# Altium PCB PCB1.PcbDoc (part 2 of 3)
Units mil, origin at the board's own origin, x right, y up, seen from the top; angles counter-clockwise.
Board outline 3586 x 4364 mil, 2 copper layers (Top Layer, Bottom Layer); 0 components, 57 nets, 205 pads, 0 vias.
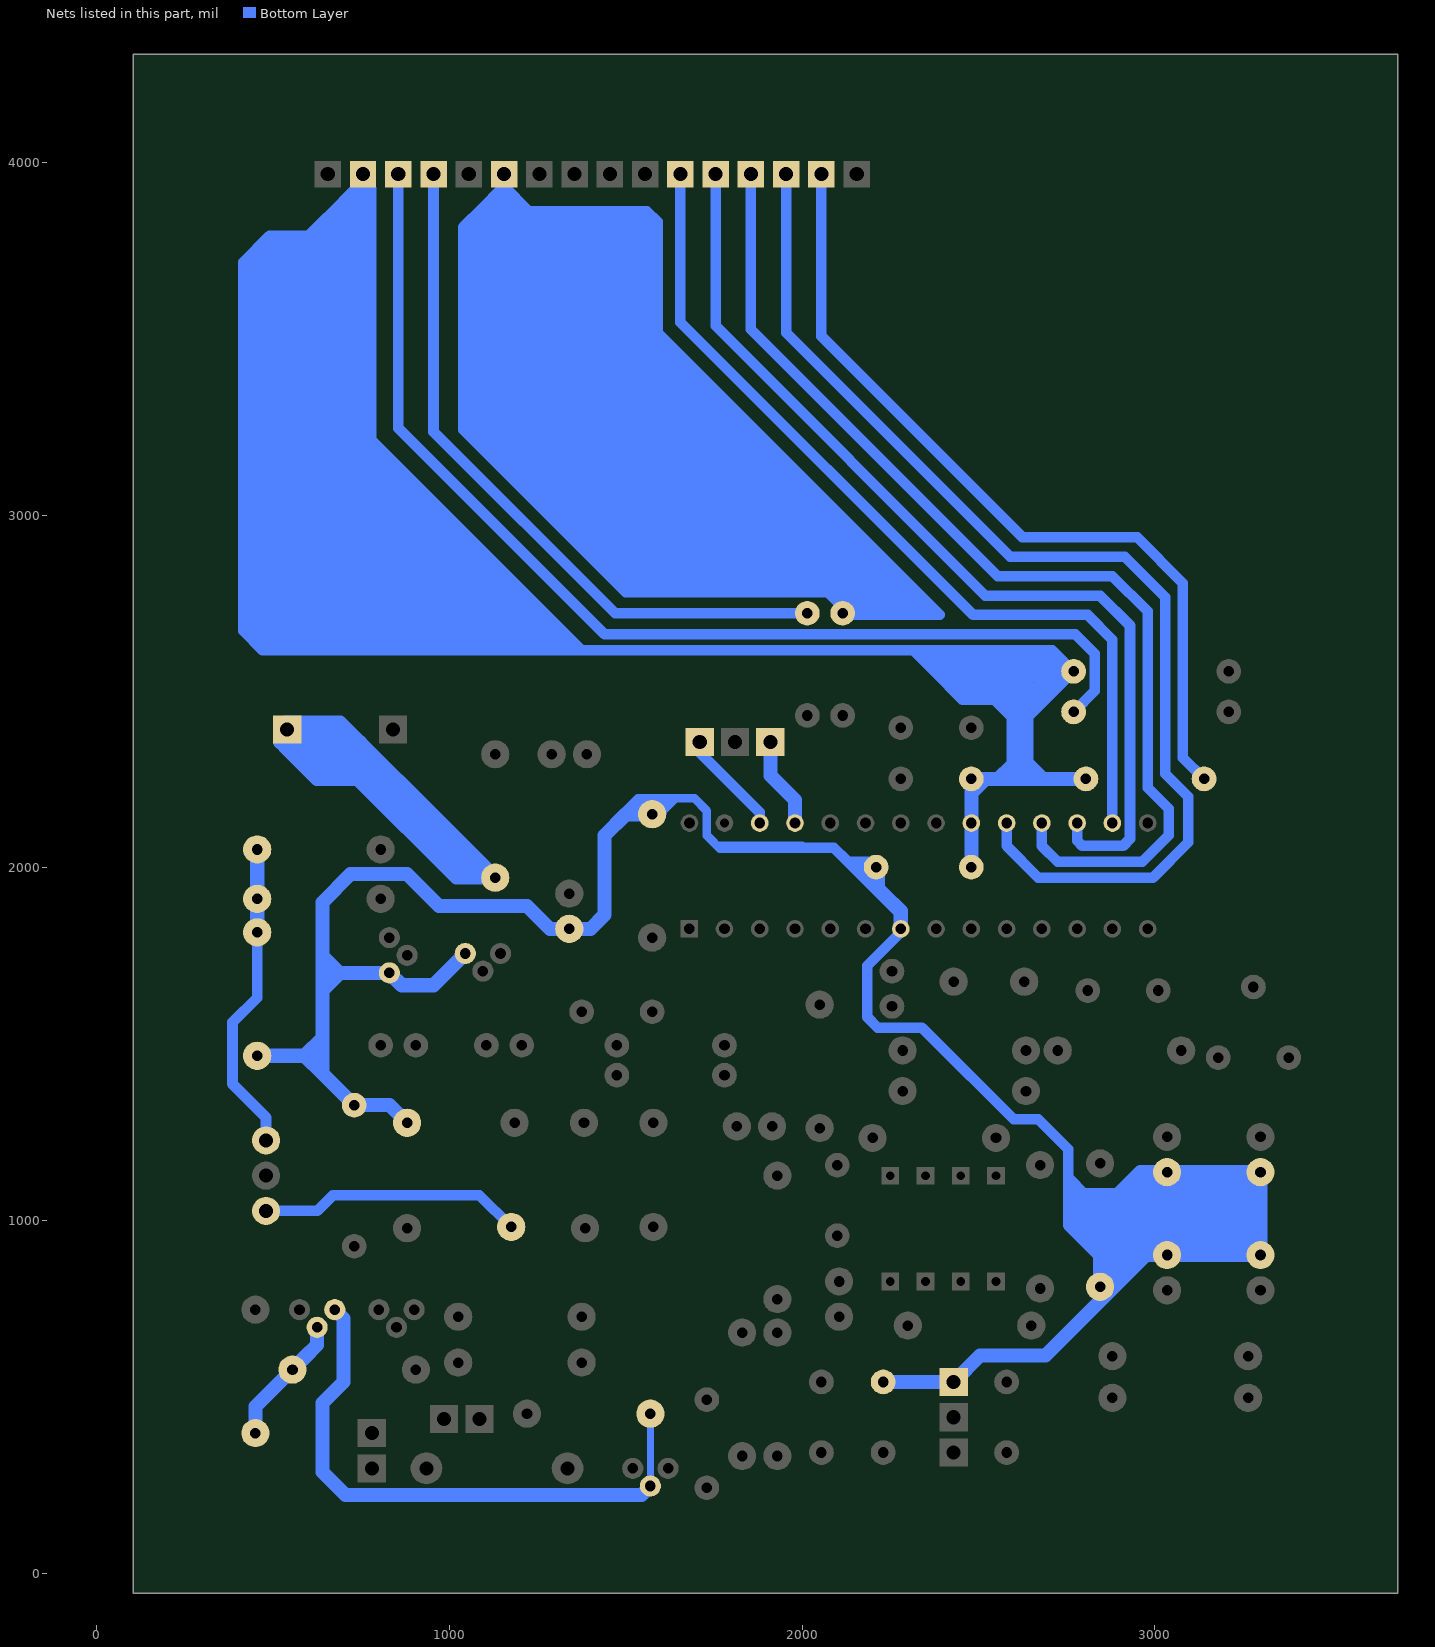
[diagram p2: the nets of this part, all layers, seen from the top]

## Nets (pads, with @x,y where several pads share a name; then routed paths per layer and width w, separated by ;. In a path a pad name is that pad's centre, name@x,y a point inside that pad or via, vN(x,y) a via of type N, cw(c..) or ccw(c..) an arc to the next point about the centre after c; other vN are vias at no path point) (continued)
$Net5: pad.1@454.35,1466.74 pad.1@729.35,1326.74 pad.1@829.35,1701.74 pad.1@879.35,1276.74 pad.1@1044.35,1756.74 pad.1@1339.35,1826.74 pad.1@1574.35,2151.74 pad.1@2209.35,2001.74 pad.1@2229.35,541.74 pad.1@2279.35,1826.74 pad.1@2429.35,541.74 pad.1@2844.35,811.74 pad.1@3034.35,901.74 pad.1@3034.35,1136.74 pad.1@3299.35,901.74 pad.1@3299.35,1136.74 | length 14800.9
  Bottom Layer w20: 2129.35,2021.74 2149.35,2021.74 ; 2134.35,2011.74 2159.35,2011.74 ; pad.1@2199.35,1971.74 2169.35,2001.74 2159.35,2011.74 ; pad.1@2214.35,2021.74 2149.35,2021.74 ; 2224.35,1941.74 2224.35,1946.74 2224.35,1966.74 ; pad.1@2224.35,2006.74 2224.35,2001.74 2224.35,1966.74 ; 2149.35,2021.74 2159.35,2011.74 ; 2159.35,2011.74 2174.35,2011.74 pad.1@2209.35,2001.74 2224.35,1966.74
  Bottom Layer w25: 1489.35,2151.74 1534.35,2196.74 1544.35,2196.74 1604.35,2196.74 1619.35,2196.74 ; 1524.35,2151.74 pad.1@1543.65,2171.04 ; 1529.35,2176.74 1534.35,2176.74 pad.1@1543.65,2171.04 ; 1564.35,2191.74 pad.1@1543.65,2171.04 ; pad.1@1589.35,2146.74 1614.35,2171.74 ; 1804.35,2054.74 1766.35,2054.74 1759.35,2061.74 ; 1999.35,2056.74 1999.35,2061.74 1759.35,2061.74 ; pad.1@1543.65,2171.04 pad.1@1574.35,2151.74 ; pad.1@1574.35,2151.74 1614.35,2171.74 ; pad.1@1574.35,2151.74 1614.35,2176.74 1634.35,2196.74 ; pad.1@1574.35,2151.74 1609.35,2186.74 1619.35,2196.74 ; 1614.35,2171.74 1624.35,2181.74 1639.35,2196.74 ; 1619.35,2196.74 1629.35,2196.74 1634.35,2196.74 ; 1634.35,2196.74 1639.35,2196.74 ; 1639.35,2196.74 1659.35,2196.74 1664.35,2196.74 1694.35,2196.74 1729.35,2161.74 1729.35,2091.74 1743.35,2077.74 1759.35,2061.74
  Bottom Layer w30: 1769.35,2056.74 1999.35,2056.74 2089.35,2056.74 2124.35,2021.74 2134.35,2011.74 2144.35,2001.74 ; pad.1@2224.35,2001.74 pad.1@2209.35,2001.74 2169.35,2001.74 2144.35,2001.74 ; pad.1@2274.35,1821.74 pad.1@2279.35,1826.74 2279.35,1816.74 2184.35,1721.74 2184.35,1576.74 2214.35,1546.74 2339.35,1546.74 2359.35,1526.74 2599.35,1286.74 2669.35,1286.74 2754.35,1201.74 2754.35,1121.74 ; 2279.35,1866.74 2144.35,2001.74 ; 2754.35,1006.74 2754.35,1061.74 ; 2764.35,1091.74 2794.35,1061.74 ; 2809.35,1046.74 2794.35,1061.74 ; 2824.35,1051.74 2814.35,1061.74 ; 2844.35,856.74 2844.35,861.74 ; 2889.35,1061.74 2814.35,1061.74 ; 2754.35,1061.74 2754.35,1086.74 2754.35,1121.74 ; 2754.35,1061.74 2759.35,1061.74 2794.35,1061.74 ; 2754.35,1121.74 2804.35,1071.74 2814.35,1061.74 ; 2794.35,1061.74 2804.35,1061.74 2814.35,1061.74
  Bottom Layer w40: pad.1@454.35,1466.74 589.35,1466.74 ; pad.1@879.35,1276.74 829.35,1326.74 764.35,1326.74 pad.1@729.35,1326.74 649.35,1406.74 639.35,1416.74 ; pad.1@1044.35,1756.74 954.35,1666.74 924.35,1666.74 899.35,1666.74 864.35,1666.74 pad.1@829.35,1701.74 689.35,1701.74 ; pad.1@1574.35,2151.74 1524.35,2151.74 1499.35,2151.74 1439.35,2091.74 1439.35,1866.74 1399.35,1826.74 pad.1@1339.35,1826.74 1284.35,1826.74 1219.35,1891.74 969.35,1891.74 879.35,1981.74 719.35,1981.74 639.35,1901.74 639.35,1749.24 ; 2159.35,1996.74 2209.35,1946.74 ; pad.1@2209.35,2001.74 2209.35,1946.74 ; pad.1@2229.35,541.74 pad.1@2429.35,541.74 2504.35,616.74 2689.35,616.74 2844.35,771.74 ; pad.1@2279.35,1826.74 2279.35,1846.74 2279.35,1866.74 2279.35,1876.74 2231.85,1924.24 2209.35,1946.74 ; 2759.35,1061.74 2759.35,1031.74 2759.35,986.74 2844.35,901.74 ; 2769.35,1011.74 2844.35,936.74 ; 2774.35,1056.74 2844.35,986.74 ; 2844.35,856.74 pad.1@2844.35,811.74 ; 2854.35,966.74 2864.35,966.74 ; 2854.35,1001.74 2864.35,1001.74 ; 2859.35,931.74 2974.35,931.74 ; 2859.35,1026.74 2924.35,1026.74 ; 2884.35,861.74 2881.85,864.24 ; 2884.35,1046.74 2889.35,1051.74 ; 2889.35,941.74 2864.35,966.74 ; 2889.35,1066.74 2894.35,1071.74 ; 2896.85,884.24 2881.85,899.24 ; 2899.35,1001.74 2924.35,1026.74 ; 2904.35,991.74 3034.35,991.74 ; 2914.35,951.74 2899.35,966.74 ; 2929.35,1066.74 2934.35,1071.74 ; 2934.35,946.74 2954.35,966.74 ; 2984.35,941.74 2974.35,931.74 ; 2989.35,1086.74 3034.35,1086.74 ; 2989.35,1126.74 2934.35,1071.74 ; pad.1@2994.35,901.74 pad.1@3034.35,901.74 ; pad.1@2999.35,901.74 2974.35,901.74 ; 3009.35,936.74 3004.35,931.74 ; 3049.35,946.74 3124.35,946.74 ; 3059.35,1056.74 3274.35,1056.74 ; 3074.35,926.74 pad.1@3034.35,901.74 ; 3079.35,926.74 3124.35,926.74 ; 3099.35,1071.74 3034.35,1071.74 ; 3144.35,1046.74 3164.35,1026.74 ; 3199.35,1051.74 3034.35,1051.74 ; 3254.35,926.74 3124.35,926.74 ; 3254.35,946.74 3244.35,946.74 ; 3259.35,966.74 3224.35,966.74 ; pad.1@3274.35,1126.74 pad.1@3274.35,1111.74 ; pad.1@3284.35,1111.74 pad.1@3274.35,1111.74 ; 3289.35,991.74 3274.35,991.74 ; pad.1@3299.35,896.74 pad.1@3299.35,901.74 ; pad.1@3304.35,1136.74 pad.1@3299.35,1136.74 ; 589.35,1466.74 639.35,1516.74 ; 589.35,1466.74 639.35,1466.74 ; 589.35,1466.74 639.35,1416.74 ; 639.35,1416.74 639.35,1466.74 ; 639.35,1466.74 639.35,1486.74 639.35,1516.74 ; 639.35,1516.74 639.35,1581.74 639.35,1651.74 ; 639.35,1651.74 639.35,1701.74 ; 639.35,1651.74 689.35,1701.74 ; 639.35,1701.74 686.85,1701.74 ; 639.35,1701.74 639.35,1721.74 639.35,1749.24 ; 639.35,1749.24 686.85,1701.74 ; 686.85,1701.74 689.35,1701.74 ; 2814.35,1051.74 2824.35,1051.74 2834.35,1051.74 2844.35,1051.74 ; 2814.35,1051.74 2804.35,1061.74 2794.35,1071.74 2804.35,1071.74 2894.35,1071.74 ; 2814.35,1051.74 2844.35,1021.74 ; 2844.35,771.74 2974.35,901.74 ; 2844.35,771.74 pad.1@2844.35,811.74 ; pad.1@2844.35,811.74 2869.35,851.74 2881.85,864.24 ; pad.1@2844.35,811.74 2884.35,841.74 2944.35,901.74 ; 2844.35,901.74 2844.35,936.74 ; 2844.35,901.74 2844.35,861.74 2864.35,881.74 ; 2844.35,901.74 2864.35,881.74 ; 2844.35,936.74 2844.35,986.74 ; 2844.35,936.74 2881.85,899.24 ; 2844.35,986.74 2844.35,1021.74 ; 2844.35,986.74 2864.35,966.74 ; 2844.35,1021.74 2864.35,1001.74 ; 2844.35,1021.74 2844.35,1051.74 ; 2844.35,1051.74 2889.35,1051.74 ; 2864.35,881.74 2869.35,886.74 2879.35,896.74 2881.85,899.24 ; 2864.35,881.74 2881.85,864.24 ; 2864.35,966.74 2899.35,966.74 ; 2864.35,1001.74 2899.35,966.74 ; 2881.85,864.24 2919.35,901.74 ; 2881.85,899.24 2884.35,901.74 2919.35,901.74 ; 2889.35,1051.74 2949.35,1051.74 ; 2889.35,1051.74 2909.35,1071.74 ; 2894.35,1071.74 2909.35,1071.74 ; 2894.35,1071.74 2959.35,1136.74 2974.35,1136.74 ; 2899.35,966.74 2954.35,966.74 ; 2909.35,1071.74 2934.35,1071.74 ; 2909.35,1071.74 2974.35,1136.74 ; 2919.35,901.74 2944.35,901.74 ; 2924.35,1026.74 2949.35,1051.74 ; 2924.35,1026.74 3034.35,1026.74 ; 2934.35,1071.74 2969.35,1071.74 ; 2944.35,901.74 2974.35,901.74 ; 2944.35,901.74 2974.35,931.74 ; 2949.35,1051.74 2969.35,1071.74 ; 2949.35,1051.74 3034.35,1051.74 ; 2954.35,966.74 2994.35,966.74 3034.35,966.74 ; 2969.35,1071.74 pad.1@3034.35,1136.74 ; 2969.35,1071.74 3034.35,1071.74 ; 2974.35,901.74 3004.35,931.74 ; 2974.35,931.74 3004.35,931.74 ; 2974.35,1136.74 pad.1@3034.35,1136.74 ; 3004.35,931.74 pad.1@3034.35,931.74 ; pad.1@3034.35,901.74 3124.35,901.74 ; pad.1@3034.35,901.74 pad.1@3034.35,931.74 ; pad.1@3034.35,931.74 3039.35,931.74 3039.35,936.74 3039.35,966.74 ; pad.1@3034.35,931.74 3034.35,966.74 ; 3034.35,966.74 3034.35,991.74 ; 3034.35,966.74 3039.35,966.74 ; 3034.35,991.74 3199.35,991.74 ; 3034.35,991.74 3034.35,1026.74 ; 3034.35,1026.74 3164.35,1026.74 ; 3034.35,1026.74 3034.35,1051.74 ; 3034.35,1051.74 3034.35,1071.74 ; 3034.35,1071.74 3034.35,1086.74 ; 3034.35,1086.74 pad.1@3034.35,1136.74 ; 3034.35,1086.74 3274.35,1086.74 ; pad.1@3034.35,1136.74 3139.35,1136.74 3149.35,1136.74 pad.1@3299.35,1136.74 ; pad.1@3034.35,1136.74 3074.35,1111.74 pad.1@3274.35,1111.74 ; 3039.35,966.74 3124.35,966.74 ; 3124.35,901.74 3214.35,901.74 pad.1@3299.35,901.74 ; 3124.35,901.74 3124.35,926.74 ; 3124.35,926.74 3124.35,946.74 ; 3124.35,946.74 3244.35,946.74 ; 3124.35,946.74 3124.35,966.74 ; 3124.35,966.74 3224.35,966.74 ; 3164.35,1026.74 3274.35,1026.74 ; 3164.35,1026.74 3199.35,991.74 ; 3199.35,991.74 3274.35,991.74 ; 3199.35,991.74 3224.35,966.74 ; 3224.35,966.74 3244.35,946.74 ; 3244.35,946.74 3259.35,931.74 pad.1@3299.35,901.74 ; 3274.35,991.74 3274.35,1026.74 ; 3274.35,991.74 3274.35,941.74 pad.1@3299.35,901.74 ; 3274.35,1026.74 3274.35,1056.74 ; 3274.35,1026.74 3299.35,1026.74 ; 3274.35,1056.74 3274.35,1086.74 ; 3274.35,1086.74 pad.1@3274.35,1111.74 ; pad.1@3299.35,901.74 3299.35,1026.74 ; 3299.35,1026.74 pad.1@3299.35,1136.74
$Net6: pad.1@454.35,1816.74 pad.1@454.35,1911.74 pad.1@454.35,2051.74 pad.1@479.35,1226.74 | length 933.3
  Bottom Layer w30: pad.1@454.35,1816.74 454.35,1631.74 384.35,1561.74 384.35,1386.74 479.35,1291.74 pad.1@479.35,1226.74
  Bottom Layer w40: pad.1@454.35,1816.74 pad.1@454.35,1911.74 ; 454.35,1871.74 pad.1@454.35,1911.74 ; pad.1@454.35,2051.74 pad.1@454.35,1911.74
$Net7: pad.1@479.35,1026.74 pad.1@1174.65,981.54 | length 751.3
  Bottom Layer w30: pad.1@479.35,1026.74 624.35,1026.74 669.35,1071.74 1084.35,1071.74 pad.1@1174.65,981.54
$Net8: pad.1@1709.35,2356.74 pad.1@1879.35,2126.74 | length 339.9
  Bottom Layer w30: pad.1@1689.35,2346.74 pad.1@1719.35,2316.74 ; pad.1@1709.35,2356.74 pad.1@1719.35,2316.74 ; pad.1@1879.35,2126.74 1879.35,2156.74 pad.1@1719.35,2316.74
$Net9: pad.1@1909.35,2356.74 pad.1@1979.35,2126.74 | length 259
  Bottom Layer w40: pad.1@1909.35,2356.74 1909.35,2261.74 1979.35,2191.74 pad.1@1979.35,2126.74
$Net10: pad.1@539.35,2391.74 pad.1@1129.35,1971.74 | length 3930.9
  Bottom Layer w30: pad.1@514.35,2356.74 514.35,2376.74 520.25,2380.34 524.35,2382.74 pad.1@539.35,2391.74
  Bottom Layer w40: pad.1@519.35,2356.74 pad.1@520.25,2355.94 ; pad.1@520.25,2380.34 pad.1@520.25,2355.94 ; pad.1@524.35,2406.74 524.35,2382.74 pad.1@524.35,2351.74 ; pad.1@534.35,2411.74 689.35,2411.74 709.35,2391.74 ; 584.35,2376.74 599.35,2361.74 ; 599.35,2341.74 619.35,2341.74 ; 659.35,2271.74 649.35,2281.74 ; 674.35,2286.74 654.35,2306.74 ; 719.35,2361.74 599.35,2361.74 ; 749.35,2341.74 619.35,2341.74 ; 804.35,2281.74 729.35,2281.74 ; 834.35,2231.74 1051.85,2014.24 ; 986.85,2014.24 1021.85,2014.24 ; 1059.35,1976.74 1021.85,2014.24 ; 1089.35,1976.74 1051.85,2014.24 ; pad.1@520.25,2355.94 pad.1@524.35,2351.74 ; pad.1@524.35,2351.74 534.35,2341.74 539.35,2336.74 ; 539.35,2336.74 544.35,2331.74 569.35,2306.74 ; 539.35,2336.74 pad.1@539.35,2391.74 ; pad.1@539.35,2391.74 624.35,2391.74 664.35,2391.74 709.35,2391.74 ; pad.1@539.35,2391.74 624.35,2306.74 ; 569.35,2306.74 584.35,2291.74 594.35,2281.74 ; 569.35,2306.74 624.35,2306.74 ; 594.35,2281.74 649.35,2281.74 ; 594.35,2281.74 624.35,2251.74 729.35,2251.74 ; 599.35,2361.74 619.35,2341.74 ; 619.35,2341.74 654.35,2306.74 ; 624.35,2306.74 654.35,2306.74 ; 624.35,2306.74 649.35,2281.74 ; 649.35,2281.74 729.35,2281.74 ; 654.35,2306.74 729.35,2306.74 ; 709.35,2391.74 734.35,2366.74 746.85,2354.24 754.35,2346.74 794.35,2306.74 ; 729.35,2251.74 739.35,2251.74 ; 729.35,2251.74 729.35,2261.74 ; 729.35,2261.74 729.35,2281.74 ; 729.35,2261.74 739.35,2251.74 ; 729.35,2281.74 729.35,2306.74 ; 729.35,2306.74 794.35,2306.74 ; 739.35,2251.74 784.35,2251.74 ; 739.35,2251.74 1019.35,1971.74 1069.35,1971.74 1099.35,1971.74 pad.1@1129.35,1971.74 1086.85,2014.24 ; 784.35,2251.74 1021.85,2014.24 ; 784.35,2251.74 849.35,2251.74 ; 794.35,2306.74 809.35,2291.74 849.35,2251.74 ; 849.35,2251.74 854.35,2246.74 1086.85,2014.24 ; 1021.85,2014.24 1051.85,2014.24 ; 1051.85,2014.24 1086.85,2014.24
$Net11: pad.1@754.35,3966.74 pad.1@2479.35,2001.74 pad.1@2479.35,2126.74 pad.1@2479.35,2251.74 pad.1@2769.35,2556.74 pad.1@2804.35,2251.74 | length 28433.2
  Bottom Layer w30: 469.35,3756.74 524.35,3756.74 ; 479.35,3681.74 516.85,3719.24 ; 484.35,3771.74 579.35,3771.74 ; 489.35,3746.74 516.85,3719.24 ; 504.35,3791.74 599.35,3791.74 ; 514.35,3691.74 524.35,3701.74 ; 519.35,3616.74 544.35,3641.74 569.35,3666.74 ; 524.35,3646.74 524.35,3701.74 ; 524.35,3766.74 524.35,3756.74 ; 574.35,3661.74 569.35,3666.74 ; 624.35,3531.74 654.35,3531.74 704.35,3531.74 734.35,3531.74 ; 629.35,3756.74 579.35,3756.74 ; 634.35,3796.74 649.35,3811.74 ; 658.35,3375.74 704.35,3375.74 734.35,3375.74 ; 659.35,3836.74 634.35,3811.74 ; 669.35,3791.74 614.35,3791.74 ; 679.35,3771.74 674.35,3771.74 ; 679.35,3811.74 649.35,3811.74 ; 719.35,3731.74 719.35,3816.74 ; 719.35,3871.74 719.35,3816.74 ; 729.35,3891.74 649.35,3811.74 ; 734.35,2651.74 734.35,2661.74 734.35,2786.74 734.35,2826.74 734.35,2911.74 734.35,3011.74 734.35,3121.74 734.35,3226.74 ; 734.35,3921.74 734.35,3831.74 ; pad.1@754.35,3976.74 pad.1@754.35,3966.74 ; 764.35,3151.74 764.35,3171.74 ; 774.35,2969.24 774.35,2971.74 774.35,3081.74 774.35,3161.74 ; 777.35,3128.74 777.35,3158.74 ; 777.35,3925.74 777.35,3213.74 ; 779.35,2961.74 781.85,2964.24 836.85,3019.24 876.85,3059.24 ; 896.85,2779.24 931.85,2814.24 986.85,2869.24 1026.85,2909.24 ; 1069.35,2711.74 1106.85,2749.24 1146.85,2789.24 ; 1129.35,2651.74 1254.35,2651.74 1284.35,2651.74 ; 1334.35,2626.74 1159.35,2801.74 ; 1369.35,2621.74 904.35,3086.74 ; 2344.35,2601.74 2640.35,2601.74 ; 2359.35,2584.24 2579.35,2584.24 ; 2456.85,2506.74 2499.35,2506.74 ; 2479.35,2481.74 2429.35,2531.74 ; 2479.35,2491.74 2514.35,2491.74 ; 2549.35,2251.74 2594.35,2296.74 ; 2559.35,2251.74 2594.35,2286.74 ; 2579.35,2451.74 2579.35,2476.74 ; 2579.35,2596.74 2579.35,2584.24 ; 2591.35,2251.74 2594.35,2254.74 ; 2594.35,2246.74 2594.35,2251.74 2594.35,2254.74 ; 2594.35,2496.74 2594.35,2491.74 ; 2604.35,2251.74 2604.35,2264.74 ; 2604.35,2481.74 2604.35,2476.74 ; 2614.35,2406.74 2604.35,2416.74 ; 2614.35,2461.74 2624.35,2471.74 ; 2619.35,2311.74 2604.35,2296.74 ; 2624.35,2285.74 2624.35,2366.74 ; 2624.35,2551.74 2624.35,2531.74 ; 2629.35,2451.74 2640.35,2462.74 ; 2634.35,2491.74 2624.35,2491.74 ; 2639.35,2351.74 2624.35,2366.74 ; 2640.35,2251.74 2640.35,2300.74 ; 2692.35,2248.74 2689.35,2251.74 2640.35,2300.74 ; 2694.35,2507.74 2689.85,2512.24 ; 2709.35,2601.74 2640.35,2601.74 ; 2714.35,2561.74 2709.35,2556.74 ; pad.1@2739.35,2561.74 pad.1@2734.35,2556.74 ; 516.85,3719.24 524.35,3726.74 ; 516.85,3719.24 524.35,3711.74 ; 524.35,3701.74 529.35,3706.74 ; 524.35,3701.74 524.35,3711.74 ; 524.35,3711.74 529.35,3706.74 ; 524.35,3711.74 524.35,3726.74 ; 524.35,3726.74 554.35,3756.74 ; 524.35,3726.74 524.35,3756.74 ; 524.35,3756.74 554.35,3756.74 ; 529.35,3706.74 579.35,3756.74 ; 529.35,3706.74 569.35,3666.74 ; 554.35,3756.74 579.35,3756.74 ; 569.35,3666.74 604.35,3701.74 654.35,3751.74 674.35,3771.74 ; 579.35,3756.74 594.35,3771.74 ; 579.35,3771.74 599.35,3791.74 ; 579.35,3771.74 594.35,3771.74 ; 594.35,3771.74 614.35,3791.74 ; 594.35,3771.74 654.35,3771.74 674.35,3771.74 ; 599.35,3791.74 619.35,3811.74 ; 599.35,3791.74 489.35,3791.74 414.35,3716.74 414.35,2671.74 469.35,2616.74 1319.35,2616.74 ; 599.35,3791.74 619.35,3811.74 ; 599.35,3791.74 614.35,3791.74 ; 614.35,3791.74 634.35,3811.74 ; 619.35,3811.74 689.35,3881.74 704.35,3896.74 pad.1@754.35,3946.74 ; 619.35,3811.74 634.35,3811.74 ; 634.35,3811.74 649.35,3811.74 ; 674.35,3771.74 704.35,3801.74 719.35,3816.74 ; 719.35,3816.74 734.35,3831.74 ; 734.35,3226.74 734.35,3375.74 ; 734.35,3226.74 754.35,3206.74 ; 734.35,3375.74 734.35,3531.74 ; 734.35,3375.74 754.35,3375.74 ; 734.35,3531.74 734.35,3831.74 ; 734.35,3531.74 754.35,3531.74 ; 734.35,3831.74 754.35,3851.74 ; 754.35,3206.74 754.35,3181.74 764.35,3171.74 ; 754.35,3206.74 764.35,3196.74 ; 754.35,3206.74 754.35,3236.74 ; 754.35,3236.74 754.35,3375.74 ; 754.35,3236.74 764.35,3226.74 ; 754.35,3375.74 754.35,3531.74 ; 754.35,3375.74 764.35,3375.74 ; 754.35,3531.74 754.35,3851.74 ; 754.35,3531.74 764.35,3531.74 ; 754.35,3851.74 pad.1@754.35,3946.74 ; pad.1@754.35,3946.74 pad.1@754.35,3966.74 ; pad.1@754.35,3966.74 774.35,3929.24 774.35,3375.74 ; pad.1@754.35,3966.74 764.35,3929.24 764.35,3531.74 ; 764.35,3171.74 774.35,3161.74 ; 764.35,3171.74 764.35,3196.74 ; 764.35,3196.74 774.35,3186.74 ; 764.35,3196.74 764.35,3226.74 ; 764.35,3226.74 764.35,3375.74 ; 764.35,3226.74 774.35,3216.74 ; 764.35,3375.74 764.35,3531.74 ; 764.35,3375.74 774.35,3375.74 ; 774.35,3161.74 777.35,3158.74 ; 774.35,3161.74 774.35,3186.74 ; 774.35,3186.74 777.35,3183.74 ; 774.35,3186.74 774.35,3216.74 ; 774.35,3216.74 774.35,3375.74 ; 774.35,3216.74 777.35,3213.74 ; 777.35,3158.74 876.85,3059.24 ; 777.35,3158.74 777.35,3183.74 ; 777.35,3183.74 889.35,3071.74 ; 777.35,3183.74 777.35,3213.74 ; 777.35,3213.74 904.35,3086.74 ; 876.85,3059.24 1026.85,2909.24 ; 876.85,3059.24 889.35,3071.74 ; 889.35,3071.74 1039.35,2921.74 ; 889.35,3071.74 904.35,3086.74 ; 1026.85,2909.24 1146.85,2789.24 ; 1026.85,2909.24 1039.35,2921.74 ; 1039.35,2921.74 1159.35,2801.74 ; 1146.85,2789.24 1284.35,2651.74 ; 1146.85,2789.24 1159.35,2801.74 ; 1284.35,2651.74 1319.35,2616.74 ; 1319.35,2616.74 1369.35,2616.74 2314.35,2616.74 ; 2314.35,2616.74 2354.35,2576.74 2374.35,2556.74 ; 2314.35,2616.74 2640.35,2616.74 ; 2374.35,2556.74 2404.35,2556.74 ; 2374.35,2556.74 2454.35,2476.74 2514.35,2476.74 2529.35,2476.74 ; 2404.35,2556.74 2579.35,2556.74 ; 2404.35,2556.74 2429.35,2531.74 ; 2429.35,2531.74 2579.35,2531.74 ; 2499.35,2506.74 2514.35,2506.74 ; 2499.35,2506.74 2514.35,2491.74 ; 2514.35,2491.74 2529.35,2491.74 ; 2514.35,2491.74 2529.35,2476.74 ; 2514.35,2506.74 2579.35,2506.74 ; 2514.35,2506.74 2529.35,2491.74 ; 2529.35,2476.74 2544.35,2476.74 ; 2529.35,2491.74 2539.35,2481.74 2544.35,2476.74 ; 2529.35,2491.74 2579.35,2491.74 ; 2544.35,2476.74 2594.35,2426.74 ; 2544.35,2476.74 2579.35,2476.74 ; 2579.35,2476.74 2594.35,2476.74 ; 2579.35,2476.74 2579.35,2491.74 ; 2579.35,2491.74 2594.35,2491.74 ; 2579.35,2491.74 2579.35,2506.74 ; 2579.35,2506.74 2624.35,2506.74 ; 2579.35,2506.74 2579.35,2531.74 ; 2579.35,2531.74 2624.35,2531.74 ; 2579.35,2531.74 2579.35,2556.74 ; 2579.35,2556.74 2640.35,2556.74 ; 2579.35,2556.74 2579.35,2584.24 ; 2579.35,2584.24 2640.35,2584.24 ; 2594.35,2254.74 2594.35,2286.74 ; 2594.35,2254.74 2604.35,2264.74 ; 2594.35,2286.74 2594.35,2296.74 ; 2594.35,2286.74 2604.35,2296.74 ; 2594.35,2296.74 2594.35,2366.74 2594.35,2396.74 ; 2594.35,2296.74 2604.35,2306.74 ; 2594.35,2396.74 2594.35,2411.74 ; 2594.35,2396.74 2604.35,2386.74 ; 2594.35,2411.74 2594.35,2426.74 ; 2594.35,2411.74 2604.35,2401.74 ; 2594.35,2426.74 2604.35,2416.74 ; 2594.35,2426.74 2594.35,2476.74 ; 2594.35,2476.74 2604.35,2476.74 ; 2594.35,2476.74 2594.35,2491.74 ; 2594.35,2491.74 2624.35,2491.74 ; 2604.35,2264.74 2604.35,2296.74 ; 2604.35,2264.74 2640.35,2300.74 ; 2604.35,2296.74 2604.35,2306.74 ; 2604.35,2306.74 2604.35,2386.74 ; 2604.35,2386.74 2604.35,2391.74 ; 2604.35,2386.74 2624.35,2366.74 ; 2604.35,2391.74 2604.35,2401.74 ; 2604.35,2391.74 2609.35,2396.74 ; 2604.35,2401.74 2609.35,2396.74 ; 2604.35,2401.74 2604.35,2404.24 2604.35,2411.74 2604.35,2416.74 ; 2604.35,2416.74 2604.35,2476.74 ; 2604.35,2476.74 2624.35,2476.74 ; 2609.35,2396.74 2624.35,2381.74 ; 2609.35,2396.74 2624.35,2411.74 ; 2624.35,2366.74 2624.35,2381.74 ; 2624.35,2381.74 2624.35,2391.74 2624.35,2411.74 ; 2624.35,2411.74 2624.35,2471.74 ; 2624.35,2411.74 2640.35,2427.74 ; 2624.35,2471.74 2624.35,2476.74 ; 2624.35,2471.74 2629.35,2476.74 ; 2624.35,2476.74 2629.35,2476.74 ; 2624.35,2476.74 2624.35,2491.74 ; 2624.35,2491.74 2624.35,2506.74 ; 2624.35,2506.74 2640.35,2506.74 ; 2624.35,2506.74 2624.35,2531.74 ; 2624.35,2531.74 2640.35,2531.74 ; 2629.35,2476.74 2640.35,2476.74 ; 2629.35,2476.74 2640.35,2487.74 ; 2640.35,2300.74 2640.35,2427.74 ; 2640.35,2427.74 2640.35,2462.74 ; 2640.35,2427.74 pad.1@2769.35,2556.74 ; 2640.35,2462.74 2689.85,2512.24 ; 2640.35,2462.74 2640.35,2476.74 ; 2640.35,2476.74 2640.35,2487.74 ; 2640.35,2487.74 2677.35,2524.74 ; 2640.35,2487.74 2640.35,2506.74 ; 2640.35,2506.74 2640.35,2531.74 ; 2640.35,2531.74 2640.35,2556.74 ; 2640.35,2556.74 2645.35,2556.74 ; 2640.35,2556.74 2640.35,2561.74 ; 2640.35,2561.74 2640.35,2584.24 ; 2640.35,2561.74 2645.35,2556.74 ; 2640.35,2584.24 2640.35,2601.74 ; 2640.35,2584.24 2741.85,2584.24 ; 2640.35,2601.74 2640.35,2616.74 ; 2640.35,2616.74 2709.35,2616.74 2741.85,2584.24 ; 2645.35,2556.74 2709.35,2556.74 ; 2645.35,2556.74 2677.35,2524.74 ; 2677.35,2524.74 2709.35,2556.74 ; 2677.35,2524.74 2689.85,2512.24 ; 2689.85,2512.24 pad.1@2734.35,2556.74 ; 2709.35,2556.74 pad.1@2734.35,2556.74 ; pad.1@2734.35,2556.74 pad.1@2769.35,2556.74 ; 2741.85,2584.24 pad.1@2769.35,2556.74
  Bottom Layer w40: 1239.35,2666.74 1254.35,2651.74 1279.35,2626.74 ; pad.1@2479.35,1991.74 2479.35,2006.74 2479.35,2024.24 2479.35,2036.74 ; pad.1@2479.35,2001.74 2479.35,2036.74 ; pad.1@2809.35,2251.74 pad.1@2804.35,2251.74 2734.35,2251.74 2689.35,2251.74 2679.35,2251.74 2640.35,2251.74 2604.35,2251.74 2594.35,2251.74 2591.35,2251.74 2559.35,2251.74 2549.35,2251.74 2519.35,2251.74 ; 2479.35,2036.74 pad.1@2479.35,2126.74 2479.35,2211.74 ; 2479.35,2211.74 pad.1@2479.35,2251.74 2519.35,2251.74 ; 2479.35,2211.74 2519.35,2251.74
  Bottom Layer w100: 459.35,2681.74 459.35,2961.74 ; 459.35,3701.74 459.35,2961.74 ; 489.35,2661.74 604.35,2661.74 ; 494.35,2681.74 494.35,2961.74 ; 494.35,3661.74 494.35,3611.74 504.35,3611.74 504.35,3141.74 ; 544.35,2691.74 544.35,2961.74 ; 544.35,3671.74 544.35,3641.74 544.35,3141.74 ; 599.35,3721.74 604.35,3701.74 604.35,3141.74 ; 624.35,2961.74 604.35,2961.74 ; 654.35,2681.74 654.35,3141.74 ; 654.35,3751.74 654.35,3531.74 654.35,3141.74 ; 704.35,2666.74 704.35,3041.74 ; 704.35,3801.74 704.35,3531.74 704.35,3375.74 704.35,3151.74 ; 734.35,2786.74 849.35,2671.74 ; 734.35,2826.74 874.35,2686.74 ; 734.35,2911.74 969.35,2676.74 ; 1069.35,2676.74 931.85,2814.24 781.85,2964.24 774.35,2971.74 734.35,3011.74 704.35,3041.74 ; 1209.35,2661.74 1194.35,2661.74 ; 459.35,2961.74 494.35,2961.74 ; 494.35,2961.74 494.35,3141.74 504.35,3141.74 ; 494.35,2961.74 544.35,2961.74 ; 504.35,3141.74 544.35,3141.74 ; 544.35,2961.74 544.35,3141.74 ; 544.35,2961.74 604.35,2961.74 ; 544.35,3141.74 604.35,3141.74 ; 604.35,2661.74 604.35,2961.74 ; 604.35,2661.74 734.35,2661.74 1194.35,2661.74 ; 604.35,2961.74 604.35,3141.74 ; 604.35,3141.74 654.35,3141.74 ; 654.35,3141.74 704.35,3141.74 ; 704.35,3041.74 704.35,3141.74 ; 704.35,3141.74 704.35,3151.74 ; 704.35,3141.74 714.35,3141.74 ; 704.35,3151.74 714.35,3141.74 ; 714.35,3141.74 734.35,3121.74 774.35,3081.74 836.85,3019.24 986.85,2869.24 1106.85,2749.24 1194.35,2661.74
$Net12: pad.1@854.35,3966.74 pad.1@2769.35,2441.74 | length 3149.9
  Bottom Layer w30: pad.1@854.35,3966.74 854.35,3246.74 1439.35,2661.74 2774.35,2661.74 2829.35,2606.74 2829.35,2501.74 pad.1@2769.35,2441.74
$Net13: pad.1@954.35,3966.74 pad.1@2014.35,2721.74 | length 2003.3
  Bottom Layer w30: pad.1@954.35,3966.74 954.35,3236.74 1469.35,2721.74 pad.1@2014.35,2721.74
$Net14: pad.1@1154.35,3966.74 pad.1@2114.35,2721.74 | length 30092.2
  Bottom Layer w30: 1049.35,3761.74 1039.35,3751.74 ; 1129.35,3161.74 1129.35,3346.74 1129.35,3506.74 1129.35,3571.74 1129.35,3711.74 1129.35,3861.74 ; pad.1@1154.35,3966.74 pad.1@1154.35,3931.74 ; 1189.35,3846.74 1209.35,3826.74 1324.35,3711.74 1384.35,3651.74 1391.85,3644.24 1413.15,3622.94 ; 1244.35,3851.74 1414.35,3681.74 1443.15,3652.94 ; 1259.35,3826.74 1224.35,3861.74 ; 1319.35,3851.74 1451.85,3719.24 1480.65,3690.44 ; 1344.35,3851.74 1464.35,3731.74 1493.15,3702.94 ; 1379.35,3851.74 1481.85,3749.24 1510.65,3720.44 ; 1404.35,3614.24 1410.65,3620.44 ; 1404.35,3851.74 1494.35,3761.74 1523.15,3732.94 ; 1434.35,3851.74 1509.35,3776.74 1538.15,3747.94 ; 1464.35,3851.74 1553.15,3762.94 ; 1489.35,3846.74 1563.15,3772.94 ; 1494.35,3541.74 1413.15,3622.94 ; 1496.85,2949.24 1526.85,2979.24 1566.85,3019.24 1604.35,3056.74 1644.35,3096.74 1686.85,3139.24 1719.35,3171.74 1756.85,3209.24 1771.85,3224.24 ; 1509.35,3851.74 1575.65,3785.44 ; 1519.35,3586.74 1589.35,3516.74 ; 1524.35,2786.74 1154.35,3156.74 ; 1539.35,3846.74 1588.15,3797.94 ; 1544.35,3551.74 1443.15,3652.94 ; 1579.35,3541.74 1455.65,3665.44 ; 1579.35,3566.74 1468.15,3677.94 ; 1579.35,3591.74 1480.65,3690.44 ; 1579.35,3616.74 1493.15,3702.94 ; 1579.35,3676.74 1523.15,3732.94 ; 1579.35,3736.74 1553.15,3762.94 ; 1584.35,3701.74 1538.15,3747.94 ; pad.1@2114.35,2716.74 2164.35,2716.74 ; 2119.35,2946.74 2114.35,2951.74 ; 2129.35,2791.74 2156.85,2764.24 ; 2149.35,2846.74 2114.35,2881.74 ; 2174.35,2861.74 2181.85,2854.24 ; 2179.35,2821.74 2196.85,2804.24 ; 2194.35,2726.74 2156.85,2764.24 ; 2201.85,2809.24 2196.85,2804.24 ; 2269.35,2721.74 2264.35,2726.74 2191.85,2799.24 ; 2309.35,2721.74 2146.85,2884.24 2114.35,2916.74 ; 2344.35,2726.74 2114.35,2956.74 ; 1039.35,3751.74 1039.35,3781.74 1039.35,3796.74 ; 1039.35,3751.74 1039.35,3721.74 1039.35,3241.74 1154.35,3126.74 ; 1039.35,3796.74 1069.35,3826.74 1104.35,3861.74 ; 1039.35,3796.74 1039.35,3806.74 ; 1039.35,3806.74 1094.35,3861.74 ; 1039.35,3806.74 1039.35,3811.74 1039.35,3816.74 1049.35,3826.74 1084.35,3861.74 ; 1084.35,3861.74 pad.1@1154.35,3931.74 ; 1084.35,3861.74 1094.35,3861.74 ; 1094.35,3861.74 1104.35,3861.74 ; 1104.35,3861.74 1154.35,3911.74 ; 1104.35,3861.74 1129.35,3861.74 ; 1129.35,3861.74 1134.35,3861.74 1154.35,3861.74 ; 1154.35,3126.74 1154.35,3156.74 ; 1154.35,3126.74 1254.35,3026.74 1499.35,2781.74 2079.35,2781.74 2099.35,2781.74 2114.35,2766.74 ; 1154.35,3156.74 1154.35,3346.74 1154.35,3506.74 1154.35,3571.74 1154.35,3711.74 1154.35,3841.74 ; 1154.35,3841.74 1284.35,3711.74 1364.35,3631.74 1489.35,3506.74 1569.35,3426.74 1771.85,3224.24 ; 1154.35,3841.74 1154.35,3861.74 ; 1154.35,3861.74 1169.35,3861.74 ; 1154.35,3861.74 1154.35,3911.74 ; 1154.35,3911.74 pad.1@1154.35,3931.74 ; 1154.35,3911.74 1204.35,3861.74 ; pad.1@1154.35,3931.74 1224.35,3861.74 ; 1169.35,3861.74 1319.35,3711.74 1381.85,3649.24 1410.65,3620.44 ; 1169.35,3861.74 1199.35,3861.74 1204.35,3861.74 ; 1204.35,3861.74 1224.35,3861.74 ; 1204.35,3861.74 1219.35,3846.74 1349.35,3716.74 1354.35,3711.74 1399.35,3666.74 1428.15,3637.94 ; 1224.35,3861.74 1239.35,3861.74 1259.35,3861.74 ; 1259.35,3861.74 1426.85,3694.24 1455.65,3665.44 ; 1259.35,3861.74 1284.35,3861.74 ; 1284.35,3861.74 1439.35,3706.74 1468.15,3677.94 ; 1284.35,3861.74 1559.35,3861.74 1589.35,3831.74 1589.35,3799.24 ; 1410.65,3620.44 1586.85,3444.24 1789.35,3241.74 ; 1410.65,3620.44 1413.15,3622.94 ; 1413.15,3622.94 1428.15,3637.94 ; 1428.15,3637.94 1604.35,3461.74 2114.35,2951.74 ; 1428.15,3637.94 1443.15,3652.94 ; 1443.15,3652.94 1455.65,3665.44 ; 1455.65,3665.44 1468.15,3677.94 ; 1468.15,3677.94 1480.65,3690.44 ; 1480.65,3690.44 1493.15,3702.94 ; 1493.15,3702.94 1510.65,3720.44 ; 1510.65,3720.44 1589.35,3641.74 ; 1510.65,3720.44 1523.15,3732.94 ; 1523.15,3732.94 1538.15,3747.94 ; 1538.15,3747.94 1553.15,3762.94 ; 1553.15,3762.94 1563.15,3772.94 ; 1563.15,3772.94 1589.35,3746.74 ; 1563.15,3772.94 1575.65,3785.44 ; 1575.65,3785.44 1589.35,3771.74 ; 1575.65,3785.44 1588.15,3797.94 ; 1588.15,3797.94 1589.35,3796.74 ; 1588.15,3797.94 1589.35,3799.24 ; 1589.35,3516.74 1589.35,3641.74 ; 1589.35,3516.74 2114.35,2991.74 ; 1589.35,3641.74 1589.35,3746.74 ; 1589.35,3746.74 1589.35,3771.74 ; 1589.35,3771.74 1589.35,3786.74 1589.35,3796.74 ; 1589.35,3796.74 1589.35,3799.24 ; 1771.85,3224.24 1811.85,3184.24 1939.35,3056.74 2114.35,2881.74 ; 1771.85,3224.24 1789.35,3241.74 ; 1789.35,3241.74 1829.35,3201.74 1956.85,3074.24 2114.35,2916.74 ; 2114.35,2766.74 pad.1@2136.85,2744.24 ; 2114.35,2766.74 2114.35,2836.74 ; 2114.35,2766.74 2114.35,2756.74 2114.35,2746.74 pad.1@2114.35,2721.74 2126.85,2734.24 pad.1@2136.85,2744.24 ; 2114.35,2836.74 2114.35,2851.74 2114.35,2876.74 ; 2114.35,2836.74 2171.85,2779.24 ; 2114.35,2876.74 2136.85,2854.24 2169.35,2821.74 2191.85,2799.24 ; 2114.35,2876.74 2114.35,2881.74 ; 2114.35,2881.74 2114.35,2916.74 ; 2114.35,2916.74 2114.35,2921.74 2114.35,2951.74 ; 2114.35,2951.74 2114.35,2956.74 ; 2114.35,2956.74 2114.35,2991.74 ; 2114.35,2991.74 2389.35,2716.74 2309.35,2716.74 2284.35,2716.74 ; pad.1@2136.85,2744.24 2164.35,2716.74 ; pad.1@2136.85,2744.24 2149.35,2756.74 2156.85,2764.24 ; 2156.85,2764.24 2171.85,2779.24 ; 2164.35,2716.74 2234.35,2716.74 ; 2171.85,2779.24 2234.35,2716.74 ; 2171.85,2779.24 2191.85,2799.24 ; 2191.85,2799.24 2196.85,2804.24 ; 2196.85,2804.24 2284.35,2716.74 ; 2234.35,2716.74 2264.35,2716.74 2284.35,2716.74
  Bottom Layer w40: 2059.35,2801.74 2079.35,2781.74 2114.35,2746.74 2126.85,2734.24 pad.1@2134.35,2726.74
  Bottom Layer w50: 1059.35,3251.74 1059.35,3346.74 ; 1059.35,3796.74 1059.35,3571.74 ; 1084.35,3711.74 1109.35,3711.74 1129.35,3711.74 1154.35,3711.74 1254.35,3711.74 1284.35,3711.74 1319.35,3711.74 1324.35,3711.74 1354.35,3711.74 ; 1109.35,3506.74 1129.35,3506.74 1154.35,3506.74 1234.35,3506.74 1239.35,3506.74 ; 1174.35,3441.74 1196.85,3464.24 1236.85,3504.24 1239.35,3506.74 ; 1309.35,3346.74 1239.35,3346.74 1154.35,3346.74 1129.35,3346.74 1109.35,3346.74 1059.35,3346.74 ; 1339.35,3196.74 1364.35,3221.74 1401.85,3259.24 1441.85,3299.24 1484.35,3341.74 1516.85,3374.24 1554.35,3411.74 1569.35,3426.74 1586.85,3444.24 1589.35,3446.74 1604.35,3461.74 ; 1359.35,3571.74 1319.35,3571.74 1304.35,3571.74 ; 1504.35,3506.74 1489.35,3506.74 1459.35,3506.74 1384.35,3506.74 1319.35,3506.74 1239.35,3506.74 ; 1509.35,3776.74 1494.35,3761.74 1481.85,3749.24 1464.35,3731.74 1451.85,3719.24 1439.35,3706.74 1426.85,3694.24 1414.35,3681.74 1399.35,3666.74 1384.35,3651.74 1381.85,3649.24 1364.35,3631.74 1349.35,3616.74 1311.85,3579.24 1304.35,3571.74 ; 1844.35,2961.74 1854.35,2971.74 1886.85,3004.24 1924.35,3041.74 1939.35,3056.74 1956.85,3074.24 1959.35,3076.74 ; 1059.35,3346.74 1059.35,3571.74 ; 1059.35,3571.74 1109.35,3571.74 1129.35,3571.74 1154.35,3571.74 1254.35,3571.74 1304.35,3571.74 ; 1239.35,3506.74 1279.35,3546.74 1304.35,3571.74
  Bottom Layer w100: 1109.35,3226.74 1109.35,3346.74 1109.35,3506.74 1109.35,3571.74 1109.35,3711.74 1109.35,3806.74 ; 1189.35,3471.74 1196.85,3464.24 1401.85,3259.24 1604.35,3056.74 1644.35,3016.74 ; 1189.35,3776.74 1254.35,3711.74 1349.35,3616.74 1459.35,3506.74 1554.35,3411.74 1756.85,3209.24 1796.85,3169.24 ; 1194.35,3311.74 1526.85,2979.24 1566.85,2939.24 ; 1194.35,3391.74 1239.35,3346.74 1364.35,3221.74 1566.85,3019.24 1606.85,2979.24 ; 1194.35,3546.74 1234.35,3506.74 1236.85,3504.24 1441.85,3299.24 1644.35,3096.74 1684.35,3056.74 ; 1194.35,3631.74 1254.35,3571.74 1279.35,3546.74 1319.35,3506.74 1484.35,3341.74 1686.85,3139.24 1726.85,3099.24 ; 1194.35,3696.74 1311.85,3579.24 1319.35,3571.74 1384.35,3506.74 1516.85,3374.24 1719.35,3171.74 1759.35,3131.74 ; 1199.35,3166.74 1496.85,2869.24 ; 1199.35,3226.74 1526.85,2899.24 ; 1484.35,2856.74 1496.85,2869.24 ; 1494.35,3541.74 1589.35,3446.74 1831.85,3204.24 ; 1544.35,2821.74 1496.85,2869.24 ; 1609.35,2816.74 1526.85,2899.24 ; 1689.35,2816.74 1566.85,2939.24 ; 1764.35,2821.74 1606.85,2979.24 ; 1839.35,2821.74 1644.35,3016.74 ; 1919.35,2821.74 1684.35,3056.74 ; 1999.35,2826.74 1854.35,2971.74 1726.85,3099.24 ; 2069.35,2821.74 1886.85,3004.24 1759.35,3131.74 ; 2119.35,2846.74 2114.35,2851.74 1924.35,3041.74 1796.85,3169.24 ; 2174.35,2861.74 2114.35,2921.74 1959.35,3076.74 1831.85,3204.24 ; 1496.85,2869.24 1526.85,2899.24 ; 1526.85,2899.24 1566.85,2939.24 ; 1566.85,2939.24 1606.85,2979.24 ; 1606.85,2979.24 1644.35,3016.74 ; 1644.35,3016.74 1684.35,3056.74 ; 1684.35,3056.74 1726.85,3099.24 ; 1726.85,3099.24 1759.35,3131.74 ; 1759.35,3131.74 1796.85,3169.24 ; 1796.85,3169.24 1811.85,3184.24 1829.35,3201.74 1831.85,3204.24
$Net15: pad.1@1654.35,3966.74 pad.1@2879.35,2126.74 | length 2537.8
  Bottom Layer w30: pad.1@1654.35,3966.74 1654.35,3546.74 2484.35,2716.74 2809.35,2716.74 2879.35,2646.74 pad.1@2879.35,2126.74
$Net16: pad.1@1754.35,3966.74 pad.1@2779.35,2126.74 | length 2776.6
  Bottom Layer w30: pad.1@1754.35,3966.74 1754.35,3536.74 2519.35,2771.74 2844.35,2771.74 2929.35,2686.74 2929.35,2081.74 2909.35,2061.74 2794.35,2061.74 2779.35,2076.74 pad.1@2779.35,2126.74
$Net17: pad.1@1854.35,3966.74 pad.1@2679.35,2126.74 | length 3030.9
  Bottom Layer w30: pad.1@1854.35,3966.74 1854.35,3526.74 2554.35,2826.74 2879.35,2826.74 2979.35,2726.74 2979.35,2226.74 3039.35,2166.74 3039.35,2091.74 2964.35,2016.74 2724.35,2016.74 2679.35,2061.74 pad.1@2679.35,2126.74
$Net18: pad.1@1954.35,3966.74 pad.1@2579.35,2126.74 | length 3216.3
  Bottom Layer w30: pad.1@1954.35,3966.74 1954.35,3516.74 2589.35,2881.74 2914.35,2881.74 3029.35,2766.74 3029.35,2266.74 3094.35,2201.74 3094.35,2071.74 2994.35,1971.74 2669.35,1971.74 2579.35,2061.74 pad.1@2579.35,2126.74
$Net19: pad.1@2054.35,3966.74 pad.1@3139.35,2251.74 | length 2354.8
  Bottom Layer w30: pad.1@2054.35,3966.74 2054.35,3506.74 2624.35,2936.74 2949.35,2936.74 3079.35,2806.74 3079.35,2311.74 pad.1@3139.35,2251.74
$Net20: pad.1@674.35,746.74 pad.1@1569.35,246.74 pad.1@1569.35,451.74 | length 1667.5
  Bottom Layer w20: pad.1@1569.35,246.74 pad.1@1569.35,451.74
  Bottom Layer w40: pad.1@674.35,746.74 699.35,721.74 699.35,541.74 639.35,481.74 639.35,286.74 704.35,221.74 1544.35,221.74 pad.1@1569.35,246.74
$Net21: pad.1@449.35,396.74 pad.1@554.35,576.74 pad.1@624.35,696.74 | length 377.5
  Bottom Layer w40: pad.1@449.35,396.74 449.35,471.74 pad.1@554.35,576.74 ; pad.1@549.35,576.74 pad.1@554.35,576.74 ; pad.1@624.35,696.74 624.35,646.74 589.35,611.74 pad.1@554.35,576.74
